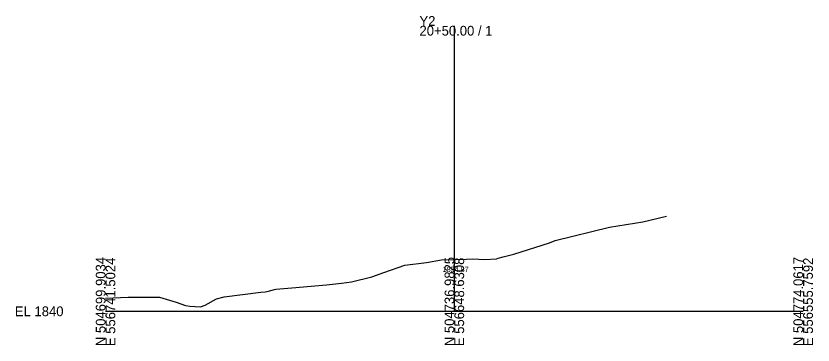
# Model space of a CAD drawing. Extents: x -26 to 1503, y -10 to 3574.
# Drawn here: x -25.7 to 202.8, y 490.3 to 584.8 of the extents above; entities that cross this region are included whole.
import ezdxf

# ---------------------------------------------------------------- set-up
doc = ezdxf.new("R2010")
doc.units = 0
for name, color, linetype in [('Default', 7, 'Continuous'), ('Exist Cross Section Cell', 7, 'Continuous'), ('Exist XS Center Line Elevation Label', 7, 'Continuous'), ('Exist XS Ground Line', 7, 'Continuous')]:
    doc.layers.add(name, color=color, linetype=linetype)

msp = doc.modelspace()

# ---------------------------------------------------------------- linework, layer by layer
at = {"layer": 'Exist Cross Section Cell'}
for p, q in [((100, 500), (100, 581.93)), ((0, 500), (100, 500)), ((100, 500), (200, 500))]:
    msp.add_line(p, q, dxfattribs=at)
at = {"layer": 'Exist XS Ground Line'}
for p, q in [((144.45, 524.1), (154.02, 525.72)), ((154.02, 525.72), (160.8, 527.31)), ((128.89, 520.29), (144.45, 524.1)), ((117.06, 516.4), (127.24, 519.65)), ((127.24, 519.65), (128.89, 520.29)), ((91.99, 513.99), (96.36, 514.75)), ((96.36, 514.75), (99.64, 514.86)), ((99.64, 514.86), (100, 514.87)), ((100, 514.87), (103.5, 514.97)), ((103.5, 514.97), (105.3, 515.08)), ((105.3, 515.08), (108.7, 514.86)), ((108.7, 514.86), (112.1, 515.05)), ((112.1, 515.05), (112.56, 515.23)), ((112.56, 515.23), (113.96, 515.61)), ((113.96, 515.61), (117.06, 516.4)), ((79.74, 511.16), (85.83, 513.23)), ((85.83, 513.23), (91.99, 513.99)), ((70.49, 508.46), (76.32, 509.94)), ((76.32, 509.94), (79.74, 511.16)), ((53.36, 506.76), (63.39, 507.56)), ((63.39, 507.56), (67.68, 508.1)), ((67.68, 508.1), (70.49, 508.46)), ((33.98, 504.16), (44.52, 505.51)), ((44.52, 505.51), (45.78, 505.57)), ((45.78, 505.57), (46.31, 505.64)), ((46.31, 505.64), (48.4, 506.25)), ((48.4, 506.25), (48.85, 506.34)), ((48.85, 506.34), (53.36, 506.76)), ((0, 503.74), (6.48, 504.02)), ((6.48, 504.02), (15.5, 504.04)), ((15.5, 504.04), (20.24, 502.6)), ((28.53, 501.73), (31.76, 503.56)), ((31.76, 503.56), (33.98, 504.16)), ((20.24, 502.6), (22.92, 501.63)), ((22.92, 501.63), (24.18, 501.46)), ((24.18, 501.46), (27.26, 501.27)), ((27.26, 501.27), (28.53, 501.73))]:
    msp.add_line(p, q, dxfattribs=at)

# ---------------------------------------------------------------- texts
at = {"layer": 'Default'}
msp.add_text('-', height=0.0001, dxfattribs=at).set_placement((0, 500))
at = {"layer": 'Exist Cross Section Cell'}
for s, p in [('Y2', (90, 581.93)), ('20+50.00 / 1', (90, 579.13)), ('EL 1840', (-26, 498.6))]:
    msp.add_text(s, height=2.8, dxfattribs=at).set_placement(p)
for s, p in [('N 504699.9034', (0, 490)), ('E 556741.5024', (2.8, 490)), ('N 504736.9825', (100, 490)), ('E 556648.6308', (102.8, 490)), ('N 504774.0617', (200, 490)), ('E 556555.7592', (202.8, 490))]:
    msp.add_text(s, height=2.8, rotation=90, dxfattribs=at).set_placement(p)
at = {"layer": 'Exist XS Center Line Elevation Label'}
msp.add_text('1854.87', height=1.5, dxfattribs=at).set_placement((96.61, 511.27))

doc.saveas('drawing.dxf')
